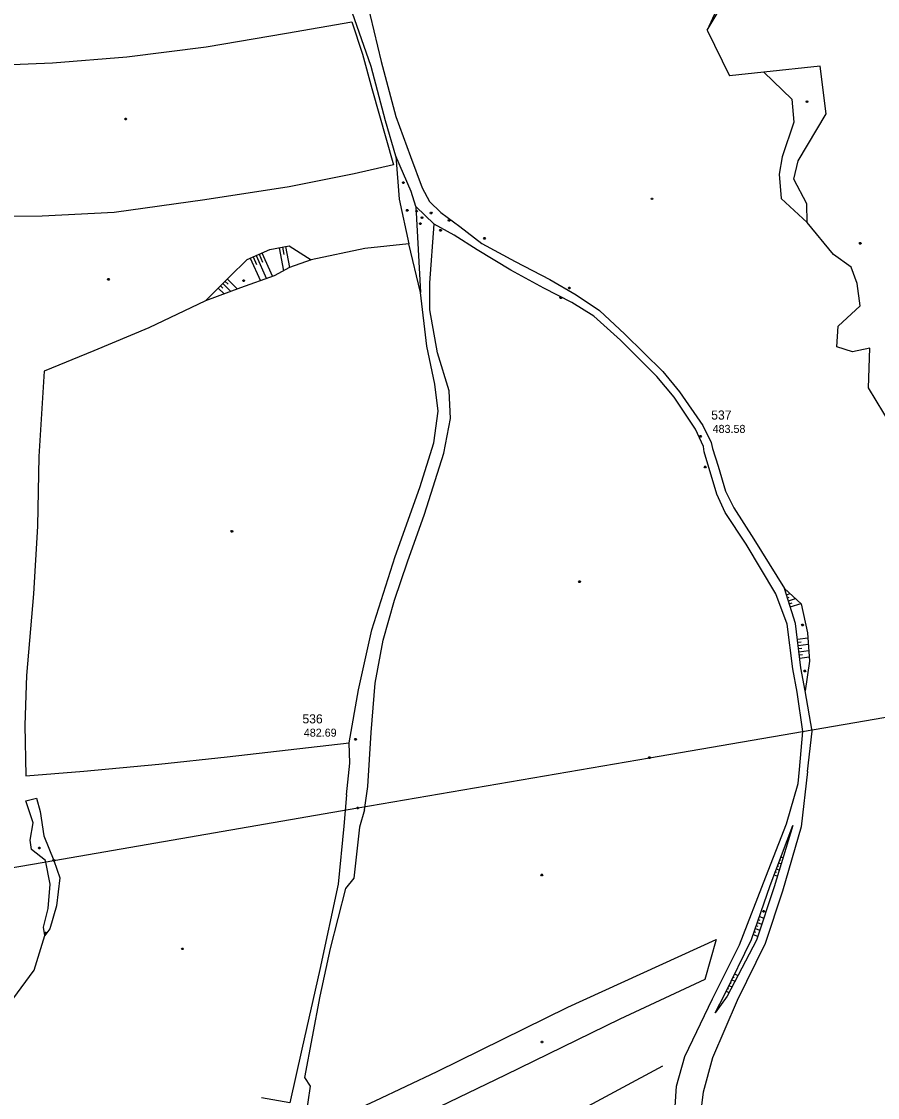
# Model space of a CAD drawing. Extents: x -664960 to -662754, y -993849 to -991145.
# Drawn here: x -663452.1 to -663131.8, y -992772.1 to -992369.4 of the extents above; entities that cross this region are included whole.
import ezdxf

# ---------------------------------------------------------------- set-up
doc = ezdxf.new("R2010")
doc.units = 0
for name, color, linetype in [('Vrstva 1', 7, 'Continuous'), ('Vrstva 12', 7, 'Continuous'), ('Vrstva 13', 7, 'Continuous'), ('Vrstva 18', 7, 'Continuous'), ('Vrstva 27', 7, 'Continuous'), ('Vrstva 37', 7, 'Continuous'), ('Vrstva 57', 7, 'Continuous'), ('Vrstva 63', 7, 'Continuous'), ('Vrstva 8', 7, 'Continuous')]:
    doc.layers.add(name, color=color, linetype=linetype)

msp = doc.modelspace()

# ---------------------------------------------------------------- linework, layer by layer
at = {"layer": 'Vrstva 12'}
msp.add_lwpolyline([(-663341.694, -992879.229), (-663337.234, -992857.288), (-663334.153, -992838.954), (-663332.511, -992826.79), (-663329.561, -992822.68), (-663308.772, -992811.806), (-663276.716, -992794.706), (-663246.682, -992778.908), (-663212.075, -992760.324)], dxfattribs=at)
at = {"layer": 'Vrstva 13'}
for points in [[(-663157.991, -992399.057), (-663157.811, -992399.357), (-663157.991, -992399.657), (-663158.351, -992399.657), (-663158.531, -992399.357), (-663158.351, -992399.057), (-663157.991, -992399.057)], [(-663412.975, -992405.534), (-663412.795, -992405.834), (-663412.975, -992406.134), (-663413.335, -992406.134), (-663413.515, -992405.834), (-663413.335, -992405.534), (-663412.975, -992405.534)], [(-663215.995, -992435.444), (-663215.815, -992435.744), (-663215.995, -992436.044), (-663216.355, -992436.044), (-663216.535, -992435.744), (-663216.355, -992435.444), (-663215.995, -992435.444)], [(-663307.603, -992439.711), (-663307.423, -992440.011), (-663307.603, -992440.311), (-663307.963, -992440.311), (-663308.143, -992440.011), (-663307.963, -992439.711), (-663307.603, -992439.711)], [(-663138.056, -992452.152), (-663137.876, -992452.452), (-663138.056, -992452.752), (-663138.416, -992452.752), (-663138.596, -992452.452), (-663138.416, -992452.152), (-663138.056, -992452.152)], [(-663419.433, -992465.542), (-663419.253, -992465.842), (-663419.433, -992466.142), (-663419.793, -992466.142), (-663419.973, -992465.842), (-663419.793, -992465.542), (-663419.433, -992465.542)], [(-663368.816, -992466.103), (-663368.636, -992466.403), (-663368.816, -992466.703), (-663369.176, -992466.703), (-663369.356, -992466.403), (-663369.176, -992466.103), (-663368.816, -992466.103)], [(-663373.21, -992559.948), (-663373.03, -992560.248), (-663373.21, -992560.548), (-663373.57, -992560.548), (-663373.75, -992560.248), (-663373.57, -992559.948), (-663373.21, -992559.948)], [(-663243.12, -992578.745), (-663242.94, -992579.045), (-663243.12, -992579.345), (-663243.48, -992579.345), (-663243.66, -992579.045), (-663243.48, -992578.745), (-663243.12, -992578.745)], [(-663158.815, -992612.189), (-663158.635, -992612.489), (-663158.815, -992612.789), (-663159.175, -992612.789), (-663159.355, -992612.489), (-663159.175, -992612.189), (-663158.815, -992612.189)], [(-663445.285, -992678.486), (-663445.105, -992678.786), (-663445.285, -992679.086), (-663445.645, -992679.086), (-663445.825, -992678.786), (-663445.645, -992678.486), (-663445.285, -992678.486)], [(-663257.224, -992688.536), (-663257.044, -992688.836), (-663257.224, -992689.136), (-663257.584, -992689.136), (-663257.764, -992688.836), (-663257.584, -992688.536), (-663257.224, -992688.536)], [(-663391.755, -992716.193), (-663391.575, -992716.493), (-663391.755, -992716.793), (-663392.115, -992716.793), (-663392.295, -992716.493), (-663392.115, -992716.193), (-663391.755, -992716.193)], [(-663257.152, -992751.023), (-663256.972, -992751.323), (-663257.152, -992751.623), (-663257.512, -992751.623), (-663257.692, -992751.323), (-663257.512, -992751.023), (-663257.152, -992751.023)]]:
    msp.add_lwpolyline(points, dxfattribs=at)
at = {"layer": 'Vrstva 18'}
for points in [[(-663304.1, -992440.07), (-663303.92, -992440.37), (-663304.1, -992440.67), (-663304.46, -992440.67), (-663304.64, -992440.37), (-663304.46, -992440.07), (-663304.1, -992440.07)], [(-663302.07, -992442.53), (-663301.89, -992442.83), (-663302.07, -992443.13), (-663302.43, -992443.13), (-663302.61, -992442.83), (-663302.43, -992442.53), (-663302.07, -992442.53)], [(-663298.66, -992440.79), (-663298.48, -992441.09), (-663298.66, -992441.39), (-663299.02, -992441.39), (-663299.2, -992441.09), (-663299.02, -992440.79), (-663298.66, -992440.79)], [(-663291.92, -992443.53), (-663291.74, -992443.83), (-663291.92, -992444.13), (-663292.28, -992444.13), (-663292.46, -992443.83), (-663292.28, -992443.53), (-663291.92, -992443.53)], [(-663295.12, -992447.25), (-663294.94, -992447.55), (-663295.12, -992447.85), (-663295.48, -992447.85), (-663295.66, -992447.55), (-663295.48, -992447.25), (-663295.12, -992447.25)], [(-663278.68, -992450.22), (-663278.5, -992450.52), (-663278.68, -992450.82), (-663279.04, -992450.82), (-663279.22, -992450.52), (-663279.04, -992450.22), (-663278.68, -992450.22)], [(-663246.94, -992468.8), (-663246.76, -992469.1), (-663246.94, -992469.4), (-663247.3, -992469.4), (-663247.48, -992469.1), (-663247.3, -992468.8), (-663246.94, -992468.8)], [(-663250.13, -992472.43), (-663249.95, -992472.73), (-663250.13, -992473.03), (-663250.49, -992473.03), (-663250.67, -992472.73), (-663250.49, -992472.43), (-663250.13, -992472.43)]]:
    msp.add_lwpolyline(points, dxfattribs=at)
at = {"layer": 'Vrstva 27'}
for points in [[(-663312.06, -992404.95), (-663306.6, -992419.9), (-663302.19, -992431.66), (-663299.49, -992436.8), (-663295.19, -992440.87), (-663288.14, -992446.15), (-663279.92, -992452.48), (-663267.33, -992459.19), (-663254.35, -992465.93), (-663244.55, -992471.72), (-663235.8, -992477.6), (-663226.33, -992486.47), (-663212.09, -992500.33), (-663205.84, -992508.01), (-663197.1, -992520.57), (-663193.98, -992526.98), (-663193.5, -992529.22), (-663191.38, -992535.82), (-663188.72, -992545.23), (-663185.52, -992551.36), (-663178.11, -992563.15), (-663166.6, -992581.64)], [(-663161.02, -992649.42), (-663159.76, -992635.15), (-663161.84, -992620.43), (-663163.46, -992611.64), (-663165.64, -992594.96), (-663169.87, -992583.61), (-663180.87, -992564.97), (-663188.82, -992553.1), (-663191.95, -992546.25), (-663196.63, -992530.4), (-663196.89, -992528.51), (-663199.91, -992521.97), (-663207.91, -992509.99), (-663214.4, -992502.31), (-663228, -992488.64), (-663237.95, -992479.63), (-663246.13, -992474.56), (-663256.68, -992469.18), (-663268.97, -992462.44), (-663281.59, -992454.9), (-663290.25, -992449.38), (-663297.65, -992445.28), (-663304.53, -992438.58), (-663306.35, -992432.98), (-663312.04, -992419.8), (-663315.95, -992406.61)], [(-663157.97, -992650.15), (-663156.19, -992634.99), (-663158.9, -992619.95)]]:
    msp.add_lwpolyline(points, dxfattribs=at)
at = {"layer": 'Vrstva 37'}
for points in [[(-663216.91, -992644.67), (-663216.73, -992644.97), (-663216.91, -992645.27), (-663217.27, -992645.27), (-663217.45, -992644.97), (-663217.27, -992644.67), (-663216.91, -992644.67)], [(-663326.14, -992663.45), (-663325.96, -992663.75), (-663326.14, -992664.05), (-663326.5, -992664.05), (-663326.68, -992663.75), (-663326.5, -992663.45), (-663326.14, -992663.45)], [(-663439.83, -992683.09), (-663439.65, -992683.39), (-663439.83, -992683.69), (-663440.19, -992683.69), (-663440.37, -992683.39), (-663440.19, -992683.09), (-663439.83, -992683.09)]]:
    msp.add_lwpolyline(points, dxfattribs=at)
at = {"layer": 'Vrstva 57'}
msp.add_lwpolyline([(-663665.051, -992722.016), (-663550.65, -992702.35), (-663440.01, -992683.39), (-663326.32, -992663.75), (-663217.09, -992644.97), (-663109.78, -992626.53), (-662986.28, -992605.36), (-662863.82, -992584.32), (-662754.25, -992565.49)], dxfattribs=at)
at = {"layer": 'Vrstva 63'}
for p, q in [((-663194.116, -992369.649), (-663193.785, -992369.799)), ((-663195.49, -992372.67), (-663187.22, -992389.65)), ((-663304.53, -992438.58), (-663302.86, -992470.84)), ((-663355.701, -992454.039), (-663354.078, -992462.651)), ((-663354.522, -992453.817), (-663354.007, -992456.552)), ((-663353.343, -992453.595), (-663351.87, -992461.41)), ((-663366.531, -992457.99), (-663362.715, -992466.448)), ((-663365.437, -992457.496), (-663364.153, -992460.343)), ((-663364.343, -992457.003), (-663360.447, -992465.64)), ((-663363.249, -992456.509), (-663361.938, -992459.415)), ((-663362.155, -992456.016), (-663358.178, -992464.833)), ((-663375.986, -992466.586), (-663374.85, -992467.716)), ((-663375.14, -992465.735), (-663371.329, -992469.525)), ((-663378.525, -992469.138), (-663376.306, -992471.345)), ((-663377.679, -992468.288), (-663376.807, -992469.154)), ((-663376.833, -992467.437), (-663373.818, -992470.435)), ((-663166.6, -992581.64), (-663166.6, -992581.64)), ((-663166.237, -992582.784), (-663166.013, -992582.713)), ((-663165.874, -992583.928), (-663164.526, -992583.5)), ((-663165.512, -992585.072), (-663164.838, -992584.858)), ((-663165.149, -992586.215), (-663162.452, -992585.36)), ((-663164.786, -992587.359), (-663163.663, -992587.003)), ((-663164.423, -992588.503), (-663160.378, -992587.22)), ((-663161.763, -992600.52), (-663157.825, -992600.044)), ((-663161.619, -992601.711), (-663160.331, -992601.556)), ((-663161.475, -992602.903), (-663157.679, -992602.444)), ((-663161.331, -992604.094), (-663160.091, -992603.944)), ((-663161.187, -992605.285), (-663157.533, -992604.844)), ((-663161.043, -992606.477), (-663159.85, -992606.333)), ((-663160.9, -992607.668), (-663157.387, -992607.244)), ((-663168.325, -992683.216), (-663168.037, -992683.324)), ((-663167.902, -992682.093), (-663167.113, -992682.39)), ((-663170.018, -992687.707), (-663169.63, -992687.854)), ((-663169.595, -992686.584), (-663168.505, -992686.995)), ((-663169.172, -992685.462), (-663168.834, -992685.589)), ((-663168.749, -992684.339), (-663167.809, -992684.693)), ((-663170.441, -992688.83), (-663169.202, -992689.298)), ((-663177.163, -992707.776), (-663176.603, -992707.972)), ((-663176.768, -992706.643), (-663175.097, -992707.226)), ((-663176.373, -992705.51), (-663175.821, -992705.703)), ((-663175.977, -992704.377), (-663174.332, -992704.951)), ((-663178.35, -992711.175), (-663176.628, -992711.776)), ((-663177.954, -992710.042), (-663177.385, -992710.24)), ((-663177.559, -992708.909), (-663175.862, -992709.501)), ((-663186.352, -992728.062), (-663185.173, -992728.639)), ((-663185.825, -992726.984), (-663185.423, -992727.181)), ((-663185.298, -992725.906), (-663184.061, -992726.511)), ((-663188.461, -992732.374), (-663187.397, -992732.895)), ((-663187.934, -992731.296), (-663187.57, -992731.474)), ((-663187.407, -992730.218), (-663186.285, -992730.767)), ((-663186.879, -992729.14), (-663186.496, -992729.328))]:
    msp.add_line(p, q, dxfattribs=at)
for points in [[(-663354.713, -992204.937), (-663349.753, -992216.812), (-663346.54, -992223.57), (-663342.09, -992235.68), (-663338.24, -992257.49), (-663334.52, -992284.83), (-663332.16, -992313.52), (-663328.01, -992334.96), (-663322.97, -992361.31), (-663317.56, -992384.35), (-663312.06, -992404.95)], [(-663315.95, -992406.61), (-663321.24, -992386.24), (-663328.39, -992365.9), (-663332.78, -992353.66), (-663334.85, -992335.84), (-663334.87, -992323.83), (-663334.49, -992314.28), (-663336.96, -992285.52), (-663340.83, -992259.95), (-663346.17, -992240.43), (-663354.039, -992225.622)], [(-663170.48, -992297.97), (-663173.25, -992305.6), (-663180.54, -992329.74), (-663185.92, -992349.84), (-663190.78, -992362.31), (-663195.49, -992372.67), (-663189.55, -992362.67), (-663184.62, -992350.04), (-663179.62, -992329.81), (-663172.2, -992305.98), (-663170.48, -992297.97)], [(-663506.96, -992386.03), (-663473.97, -992386.18), (-663440.6, -992384.86), (-663412.71, -992382.62), (-663383.01, -992378.86), (-663352.92, -992373.77), (-663328.49, -992369.51), (-663324.56, -992381.56), (-663321.02, -992394.46), (-663312.91, -992423.04), (-663327.66, -992426.41), (-663351.95, -992431.22), (-663383.52, -992436.14), (-663417.4, -992440.81), (-663444.41, -992442.2), (-663467.36, -992442.46), (-663488.2, -992442.47), (-663504.16, -992440.08)], [(-663125.7, -992522.95), (-663126.5, -992520.73), (-663135.09, -992506.52), (-663134.6, -992491.67), (-663141.11, -992493.05), (-663146.95, -992491.13), (-663146.44, -992483.47), (-663138.21, -992475.77), (-663139.42, -992467.43), (-663141.6, -992461.31), (-663148.26, -992456.54), (-663158.14, -992444.66), (-663158.22, -992437.59), (-663163.14, -992428.35), (-663161.52, -992421.55), (-663151.04, -992403.91), (-663153.25, -992386.13), (-663174.26, -992388.31), (-663187.22, -992389.65)], [(-663174.26, -992388.31), (-663163.84, -992398.4), (-663163.08, -992407.03), (-663167.46, -992419.97), (-663168.56, -992426.51), (-663167.89, -992435.68), (-663158.14, -992444.66)], [(-663312.04, -992419.8), (-663310.75, -992435.84), (-663307.19, -992452.64)], [(-663309.06, -992429.38), (-663308.88, -992429.68), (-663309.06, -992429.98), (-663309.42, -992429.98), (-663309.6, -992429.68), (-663309.42, -992429.38), (-663309.06, -992429.38)], [(-663323.76, -992664.43), (-663322.49, -992655.76), (-663321.29, -992635.56), (-663319.76, -992617.08), (-663316.78, -992600.96), (-663312.51, -992586.03), (-663307.71, -992571.59), (-663301.37, -992553.79), (-663294.09, -992530.98), (-663291.55, -992517.96), (-663292.05, -992507.62), (-663296.46, -992493.34), (-663299.29, -992477.3), (-663299.38, -992467.22), (-663297.65, -992445.28)], [(-663302.71, -992444.76), (-663302.53, -992445.06), (-663302.71, -992445.36), (-663303.07, -992445.36), (-663303.25, -992445.06), (-663303.07, -992444.76), (-663302.71, -992444.76)], [(-663383.24, -992473.88), (-663404.5, -992484.02), (-663425.05, -992492.61), (-663443.66, -992500.26), (-663445.66, -992532.22), (-663446.15, -992558.29), (-663447.68, -992583.58), (-663450.28, -992614.15), (-663450.95, -992632.72), (-663450.56, -992651.7), (-663428.86, -992649.98), (-663400.7, -992647.39), (-663375.15, -992644.6), (-663352.28, -992641.95), (-663329.55, -992639.44), (-663326.01, -992619.49), (-663321.03, -992597.07), (-663312.29, -992569.6), (-663303.02, -992543.75), (-663297.86, -992527.09), (-663296.23, -992515.29), (-663297.42, -992505.12), (-663300.39, -992490.94), (-663302.86, -992470.84), (-663307.19, -992452.64)], [(-663383.24, -992473.88), (-663374.31, -992464.9), (-663367.64, -992458.49), (-663359.26, -992454.71), (-663351.99, -992453.34), (-663343.71, -992458.59)], [(-663307.19, -992452.64), (-663323.71, -992454.34), (-663343.71, -992458.59)], [(-663343.71, -992458.59), (-663351.87, -992461.41), (-663357.58, -992464.62), (-663370.14, -992469.09), (-663383.24, -992473.88)], [(-663196.1, -992535.81), (-663195.92, -992536.11), (-663196.1, -992536.41), (-663196.46, -992536.41), (-663196.64, -992536.11), (-663196.46, -992535.81), (-663196.1, -992535.81)], [(-663158.9, -992619.95), (-663160.46, -992611.31), (-663162.47, -992594.66), (-663166.6, -992581.64), (-663160.3, -992587.29), (-663157.94, -992598.15), (-663157.29, -992608.83), (-663158.9, -992619.95)], [(-663159.63, -992595.02), (-663159.45, -992595.32), (-663159.63, -992595.62), (-663159.99, -992595.62), (-663160.17, -992595.32), (-663159.99, -992595.02), (-663159.63, -992595.02)], [(-663330.52, -992658.89), (-663329.32, -992647.01), (-663329.55, -992639.44)], [(-663165.68, -992963.32), (-663170.73, -992947.56), (-663181.47, -992915.18), (-663188.89, -992890.63), (-663198.63, -992854.33), (-663204.3, -992827.65), (-663206.76, -992813.18), (-663208.61, -992792.75), (-663207.05, -992767.88), (-663203.88, -992756.76), (-663193.47, -992735.2), (-663183.37, -992715.05), (-663173.54, -992689.58), (-663165.8, -992669.68), (-663161.51, -992654.55), (-663161.02, -992649.42)], [(-663157.97, -992650.15), (-663160.41, -992670.84), (-663167.3, -992694.91), (-663173.84, -992714.52), (-663184.29, -992735.8), (-663193.55, -992757.24), (-663197.08, -992770.11), (-663199.83, -992791.76), (-663199.1, -992811.89), (-663197.29, -992826.55), (-663191.72, -992853.3), (-663180.73, -992887.82), (-663172.94, -992913.46), (-663163.04, -992945.97), (-663161.22, -992950.26)], [(-663330.52, -992658.89), (-663331.495, -992670.602), (-663333.676, -992692.339), (-663340.522, -992724.223), (-663347.204, -992754.01), (-663351.708, -992774.127), (-663362.346, -992772.219)], [(-663450.58, -992661.1), (-663446.51, -992660.1), (-663445.1, -992665.08), (-663443.81, -992674.16), (-663440.01, -992683.39), (-663437.82, -992689.95), (-663439.05, -992700.35), (-663441.57, -992709.04), (-663443.35, -992711.5), (-663443.95, -992708.33), (-663442.22, -992701.44), (-663441.4, -992692.27), (-663443.2, -992683.4), (-663448.44, -992679.34), (-663448.84, -992675.76), (-663447.75, -992669.27), (-663450.58, -992661.1)], [(-663323.76, -992664.43), (-663325.651, -992670.965), (-663327.75, -992690.031), (-663330.921, -992693.862), (-663336.578, -992716.329), (-663340.507, -992734.162), (-663346.25, -992764.677), (-663344.145, -992767.919), (-663348.518, -992797.833)], [(-663163.45, -992670.28), (-663170.4, -992693.26), (-663177.11, -992713.21), (-663188.09, -992734.22), (-663192.53, -992740.48), (-663189.09, -992733.66), (-663178.99, -992713.01), (-663171.93, -992692.78), (-663163.45, -992670.28)], [(-663174.21, -992702.13), (-663174.03, -992702.43), (-663174.21, -992702.73), (-663174.57, -992702.73), (-663174.75, -992702.43), (-663174.57, -992702.13), (-663174.21, -992702.13)], [(-663484.479, -992778.312), (-663476.949, -992760.827), (-663462.91, -992742.863), (-663455.403, -992735.348), (-663447.365, -992724.436), (-663443.35, -992711.5)], [(-663442.986, -992710.307), (-663442.806, -992710.607), (-663442.986, -992710.907), (-663443.346, -992710.907), (-663443.526, -992710.607), (-663443.346, -992710.307), (-663442.986, -992710.307)], [(-663341.06, -992795.72), (-663339.812, -992782.68), (-663319.813, -992773.344), (-663296.571, -992762.399), (-663247.704, -992738.275), (-663192.139, -992712.934), (-663196.342, -992728.012), (-663228.245, -992742.866), (-663271.078, -992763.781), (-663316.391, -992785.583), (-663341.06, -992795.72)]]:
    msp.add_lwpolyline(points, dxfattribs=at)
at = {"layer": 'Vrstva 8'}
for points in [[(-663197.84, -992524.33), (-663197.66, -992524.63), (-663197.84, -992524.93), (-663198.2, -992524.93), (-663198.38, -992524.63), (-663198.2, -992524.33), (-663197.84, -992524.33)], [(-663326.95, -992637.8), (-663326.77, -992638.1), (-663326.95, -992638.4), (-663327.31, -992638.4), (-663327.49, -992638.1), (-663327.31, -992637.8), (-663326.95, -992637.8)]]:
    msp.add_lwpolyline(points, dxfattribs=at)

# ---------------------------------------------------------------- texts
at = {"layer": 'Vrstva 1'}
for s, p in [('537', (-663194.01, -992518.382)), ('536', (-663347.003, -992632.101))]:
    msp.add_text(s, height=3.4, dxfattribs=at).set_placement(p)
at = {"layer": 'Vrstva 63'}
for s, p in [('483.58', (-663193.486, -992523.362)), ('482.69', (-663346.479, -992637.081))]:
    msp.add_text(s, height=3, dxfattribs=at).set_placement(p)

doc.saveas('drawing.dxf')
